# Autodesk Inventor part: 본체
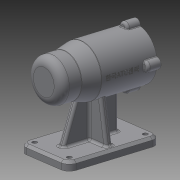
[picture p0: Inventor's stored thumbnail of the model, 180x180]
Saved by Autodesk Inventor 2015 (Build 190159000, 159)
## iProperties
Created: 2019-07
Part Number: 본체
Material: 일반
Document SubType Name: Modeling
Designer: now
Density: 1 g/cm^3
Appearance: 기본값
Author: now
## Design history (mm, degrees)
sketch "스케치1"
  geometry: C1 r 30 at (0, 0); 1 further point
  constraints: 1 centre point, 1 coincident
  dimensions: "d0" = 60 diameter of C1
extrude "돌출1" new body sketch "스케치1" distance "d1" = 67; taper "d2" = 0 deg
node "작업 평면1"
sketch "스케치3"
  geometry: C1 r 25 at (0, 0); 1 further point
  constraints: 1 centre point, 1 coincident
  dimensions: "d4" = 50 diameter of C1
extrude "돌출2" join sketch "스케치3" distance "d5" = 25; taper "d6" = 0 deg
sketch "스케치6"
  geometry: L1 (30, 67)-(30, 0) reference; L2 (30, 0)-(-30, 0) reference; L3 (-30, 0)-(-30, 67) reference; L4 (-30, 67)-(30, 67) reference; L5 (-25, 87)-(-25, 112) reference; L6 (-25, 112)-(25, 112) reference; L7 (25, 112)-(25, 87) reference; L8 (25, 87)-(-25, 87) reference; L9 (25, 87)-(30, 67); L10 (0, 112)-(0, 0)
  constraints: 4 end point, 1 midpoint, 1 vertical
revolve "회전1" sketch "스케치6" stored, may be unused: angle "d7" = 90 deg
node "작업 평면2"
sketch "스케치7"
  geometry: L1 (35, 112)-(-35, 112); L2 (-35, 112)-(-35, 0); L3 (-35, 0)-(35, 0); L4 (35, 0)-(35, 112); 2 further points
  constraints: 8 end point, 2 coincident, 2 parallel, 1 horizontal, 1 midpoint, 1 perpendicular
  dimensions: "d9" = 70 distance of L2.end L3.end; "d10" = 112 distance of L3.end L1.start
extrude "돌출3" join sketch "스케치7" distance "d11" = 10; taper "d12" = 0 deg
fillet "모깎기1" dims "d13" = 10
sketch "스케치8"
  geometry: A1 r 10 centre (-25, -10) between (-25, 0) and (-35, -10) reference; A2 r 10 centre (-25, -102) between (-35, -102) and (-25, -112) reference; A3 r 10 centre (25, -102) between (25, -112) and (35, -102) reference; A4 r 10 centre (25, -10) between (35, -10) and (25, 0) reference; 1 further point
hole "구멍1" sketch "스케치8" at (-25, -102), (25, -102), (25, -10), (-25, -10) diameter "d14" = 6; stored, may be unused: countersink angle "d18" = 90 deg, drill point angle "d20" = 118 deg; dims "d15" = 6, "d16" = 4, "d17" = 2, "d19" = 8
sketch "스케치9"
  geometry: L1 (-35, -10)-(-35, -102) reference; L2 (-25, -112)-(25, -112) reference; L3 (35, -102)-(35, -10) reference; L4 (25, 0)-(-25, 0) reference; L5 (-28, -60)-(28, -60); L6 (28, -60)-(28, -52); L7 (28, -52)-(-28, -52); L8 (-28, -52)-(-28, -60); L9 (-4, -92)-(4, -92); L10 (4, -92)-(4, -25); L11 (4, -25)-(-4, -25); L12 (-4, -25)-(-4, -92); 7 further points
  constraints: 16 end point, 6 midpoint, 4 parallel, 2 horizontal, 2 perpendicular, 1 horizontal alignment, 1 vertical alignment
  dimensions: "d21" = 8 distance of L7.end L5.start; "d22" = 7 distance between parallel lines of L1 L8; "d23" = 8 distance of L10.end L11.end; "d24" = 25 distance between parallel lines of L4 L11; "d25" = 20 distance between parallel lines of L2 L9; "d26" = 31 distance between parallel lines of L1 L12
extrude "돌출4" join sketch "스케치9" stored distance "d27" = 10; taper "d28" = 0 deg
feature "면 기울기1" dims angle "d29" = 20 deg
feature "면 기울기2" dims angle "d30" = 10 deg
sketch "스케치10"
  geometry: C1 r 6 at (0, 30); C2 r 6 at (-30, 0); C3 r 6 at (0, -30); C4 r 6 at (30, 0); 1 further point
  constraints: 4 centre point, 2 vertical alignment, 10 other
  dimensions: "d31" = 12 diameter of C1; "d34" = 360 deg dimension on point (0, 0) C1.centre (derived)
extrude "돌출5" join sketch "스케치10" distance "d36" = 16; taper "d37" = 0 deg
fillet "모깎기2" dims "d38" = 10
fillet "모깎기3" dims "d39" = 3
fillet "모깎기4" dims "d40" = 1
fillet "모깎기5" dims "d41" = 3
fillet "모깎기6" dims "d42" = 3
sketch "스케치11"
  geometry: A1 r 30 centre (0, 0) between (29.226, 6.771) and (6.771, 29.226) reference; 1 further point
  constraints: 1 vertical alignment
  dimensions: "d43" = 30 distance of A1.centre point (0, 30)
hole "구멍2" sketch "스케치11" at (0, 30) diameter "d44" = 3.242; stored, may be unused: countersink angle "d48" = 90 deg, drill point angle "d50" = 118 deg; dims "d45" = 8, "d46" = 4, "d47" = 2, "d49" = 11
sketch "스케치12"
  geometry: L1 (25, 102)-(25, 87) reference; L2 (25, 87)-(30, 67) reference; L3 (30, 67)-(30, 17) reference; L4 (31, 16)-(33, 16) reference; L5 (36, 13)-(36, 0) reference; L6 (36, 0)-(31.621, 0) reference; L7 (31.621, 0)-(31.621, 11) reference; L8 (31.621, 11)-(30, 11.974) reference; L9 (30, 11.974)-(28.379, 11) reference; L10 (28.379, 11)-(28.379, 0) reference; L11 (28.379, 0)-(-28.379, 0) reference; L12 (-28.379, 0)-(-28.379, 11) reference; L13 (-28.379, 11)-(-30, 11.974) reference; L14 (-30, 11.974)-(-31.621, 11) reference; L15 (-31.621, 11)-(-31.621, 0) reference; L16 (-31.621, 0)-(-36, 0) reference; L17 (-36, 0)-(-36, 13) reference; L18 (-33, 16)-(-31, 16) reference; L19 (-30, 17)-(-30, 25) reference; L20 (-30, 25)-(-67, 25) reference; L21 (-70, 22)-(-70, 0) reference; L22 (-70, 0)-(-80, 0) reference; L23 (-80, 0)-(-80, 112) reference; L24 (-80, 112)-(-70, 112) reference; L25 (-70, 112)-(-70, 94.101) reference; L26 (-68.026, 91.282)-(-27.607, 76.57) reference; L27 (-27.607, 76.57)-(-25, 87) reference; L28 (-25, 87)-(-25, 102) reference; L29 (-15, 112)-(15, 112) reference; L30 (0, 112)-(0, 0); L31 (21, 0)-(21, 15); L32 (21, 15)-(24, 15); L33 (24, 15)-(24, 69); L34 (24, 69)-(21, 69); L35 (21, 69)-(21, 81); L36 (21, 81)-(17.5, 81); L37 (17.5, 81)-(17.5, 99); L38 (17.5, 99)-(16, 99); L39 (16, 99)-(16, 103); L40 (16, 103)-(10.5, 103); L41 (10.5, 103)-(10.5, 106); L42 (10.5, 106)-(0, 106); L43 (0, 106)-(0, 0); L44 (21, 0)-(0, 0); L45 (1.621, 0)-(-1.621, 0) reference; A1 r 10 centre (15, 102) between (25, 102) and (15, 112) reference; A2 r 1 centre (31, 17) between (30, 17) and (31, 16) reference; A3 r 3 centre (33, 13) between (36, 13) and (33, 16) reference; A4 r 3 centre (-33, 13) between (-33, 16) and (-36, 13) reference; A5 r 1 centre (-31, 17) between (-31, 16) and (-30, 17) reference; A6 r 3 centre (-67, 22) between (-67, 25) and (-70, 22) reference; A7 r 3 centre (-67, 94.101) between (-70, 94.101) and (-68.026, 91.282) reference; A8 r 10 centre (-15, 102) between (-15, 112) and (-25, 102) reference
  constraints: 30 end point, 11 perpendicular, 2 collinear, 2 point on line, 2 vertical, 1 midpoint
  dimensions: "d54" = 15 distance of L31.start L31.end; "d55" = 3 distance of L40.end L41.end; "d56" = 4 distance of L38.end L39.end; "d57" = 18 distance of L36.end L37.end; "d58" = 12 distance of L34.end L35.end; "d59" = 54 distance of L32.end L33.end; "d60" = 21 diameter of L41 L30; "d61" = 32 diameter of L39 L30; "d62" = 35 diameter of L37 L30; "d63" = 42 diameter of L35 L30; "d64" = 48 diameter of L33 L30; "d65" = 42 diameter of L31 L30
revolve "회전2" sketch "스케치12" stored, may be unused: angle "d66" = 90 deg
fillet "모깎기7" dims "d67" = 0.3
fillet "모깎기8" dims "d68" = 3
chamfer "모따기1" distance "d69" = 3; stored, may be unused: second distance "d70" = 2, angle "d71" = 45 deg
chamfer "모따기2" distance "d72" = 1; stored, may be unused: second distance "d73" = 2, angle "d74" = 45 deg
node "작업 평면3"
sketch "스케치13"
  geometry: L1 (6.771, 0)-(29.226, 0) reference; L2 (5.998, 0)-(-5.998, 0) reference; 3 further points
  constraints: 1 midpoint, 1 vertical alignment, 1 other
  dimensions: "d76" = 42 distance from line of point (0, 42) L1
feature "엠보싱1" sketch "스케치13" dims "d77" = 0.5, "d78" = 0
fillet "모깎기9" dims "d79" = 3
node "솔리드1"
pattern_circular "원형 패턴1" dims angle "d52" = 360 deg
node "절단 모서리 투영2"
node "절단 모서리 투영3"
other parameters: "d3" = 112
